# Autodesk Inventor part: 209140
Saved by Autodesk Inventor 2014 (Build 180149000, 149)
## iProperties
Shininess: 64.0
Length Units: 11272
Angle Units: 11279
Time Units: 11290
Mass Units: 11286
Length Display Precision: 3
Angle Display Precision: 2
Company: Autodesk, Inc.
Created: 2001-12
Part Number: 209140
Material: Steel, Mild
Description: FITTING; MC-G24-S
Document SubType Name: Modeling
Designer: Autodesk, Inc.
Density: 7.86 g/cm^3
Mass: 552.218 g
Surface Area: 104.821 cm^2
Volume: 70.2567 cm^3
Appearance: Yellow Zinc
Density: 7.75
Volumn: 1.1899929784618444
Area: 7.049002142317107
PropertySet Name: Model Information
Control State: 0
Master: False
Checked Out: False
Last Check In By: JT
Last Check In Date: 2003-06-20
Title: FITTING; MC-G24-S
Author: Autodesk, Inc.
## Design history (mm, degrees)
derived "MC-G.ipt"
body "Solid1"
tag "TaggingFeature2"
feature "Solid1::MC-G.ipt" dims "ScaleForDerivedMember" = 10
